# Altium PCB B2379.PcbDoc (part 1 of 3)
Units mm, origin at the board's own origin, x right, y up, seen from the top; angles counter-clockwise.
Board outline 50 x 95 mm, 4 copper layers (Top Layer 1 Signal, Layer 2, Layer 3, Bottom Layer 4 Signal), stack 1.536 mm thick; 177 components, 121 nets, 523 pads, 969 vias.
Unrouted connection lines stored in the file: 25.
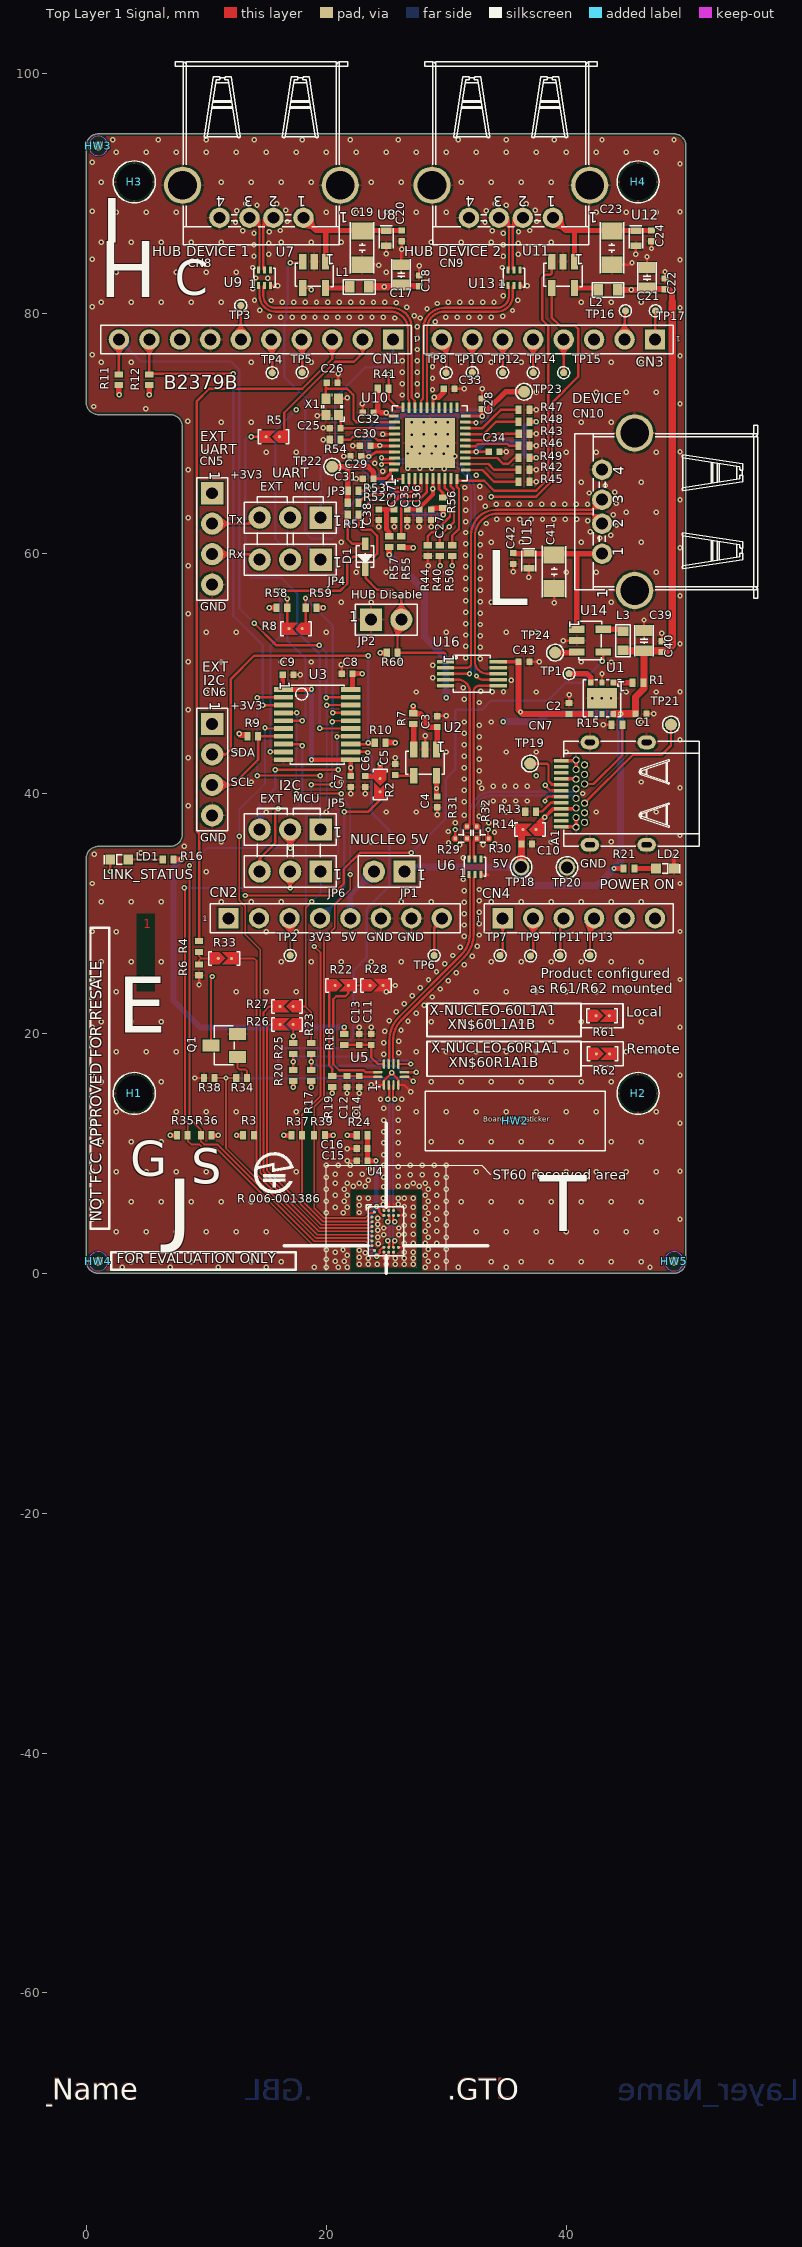
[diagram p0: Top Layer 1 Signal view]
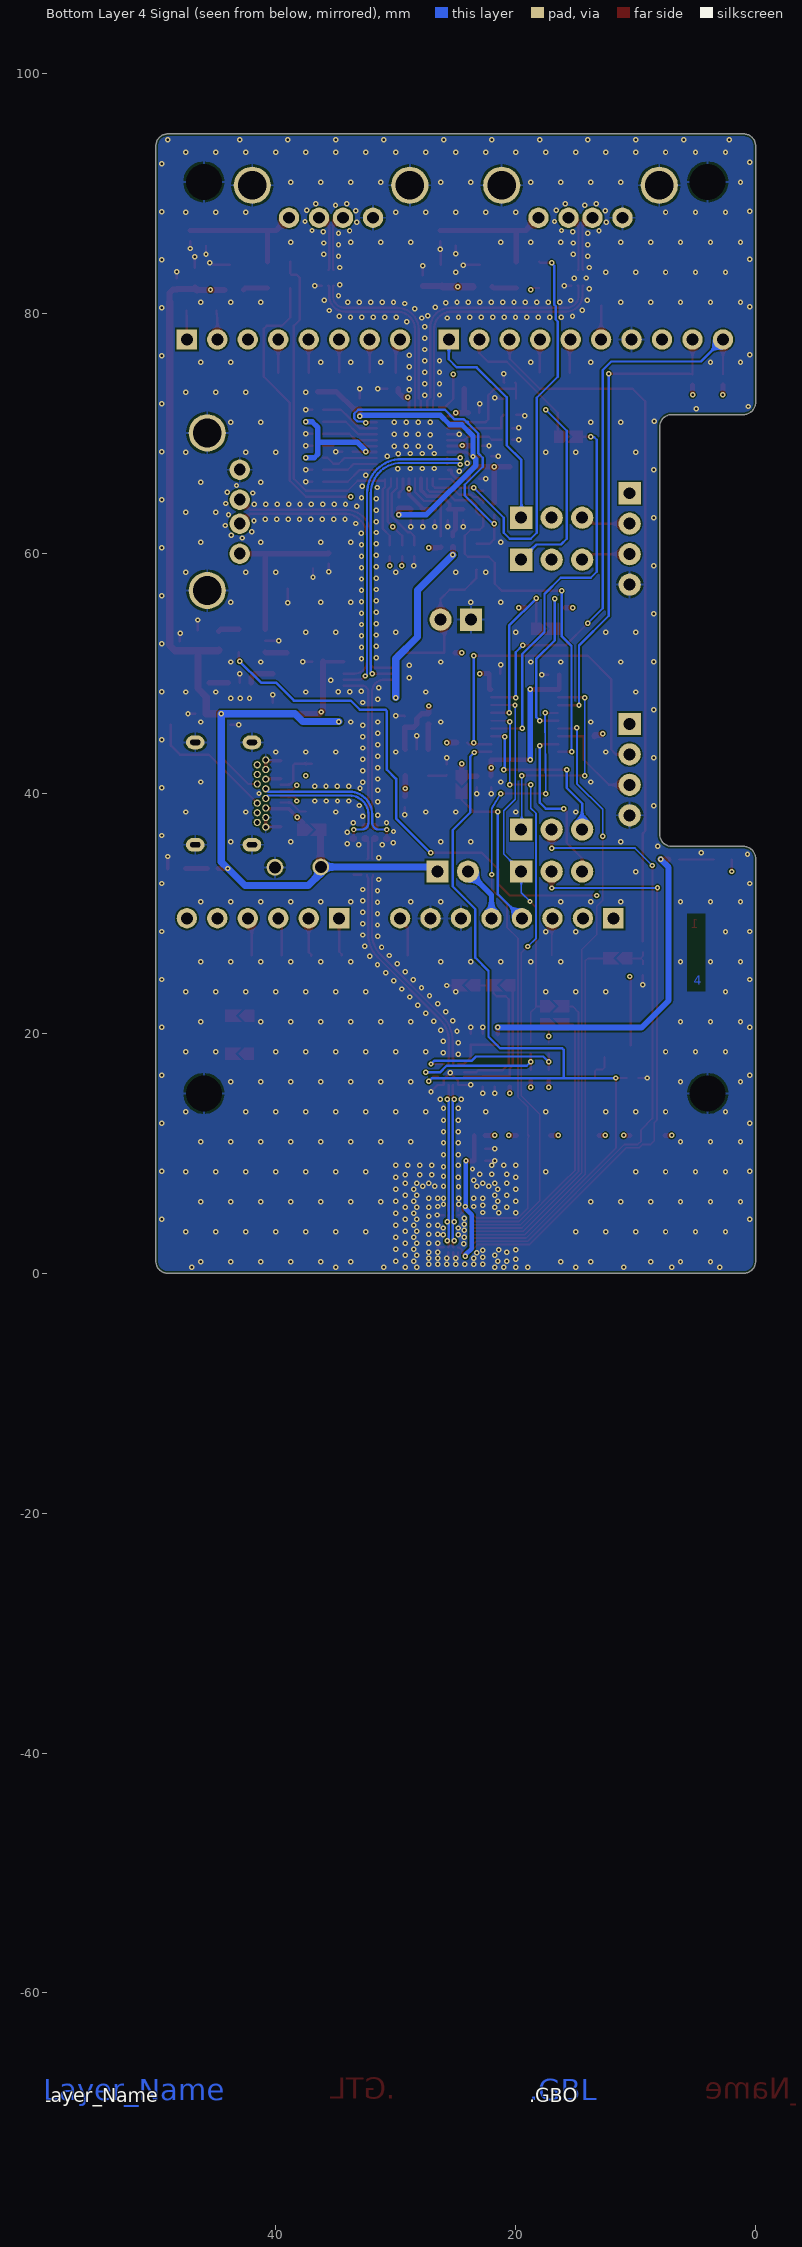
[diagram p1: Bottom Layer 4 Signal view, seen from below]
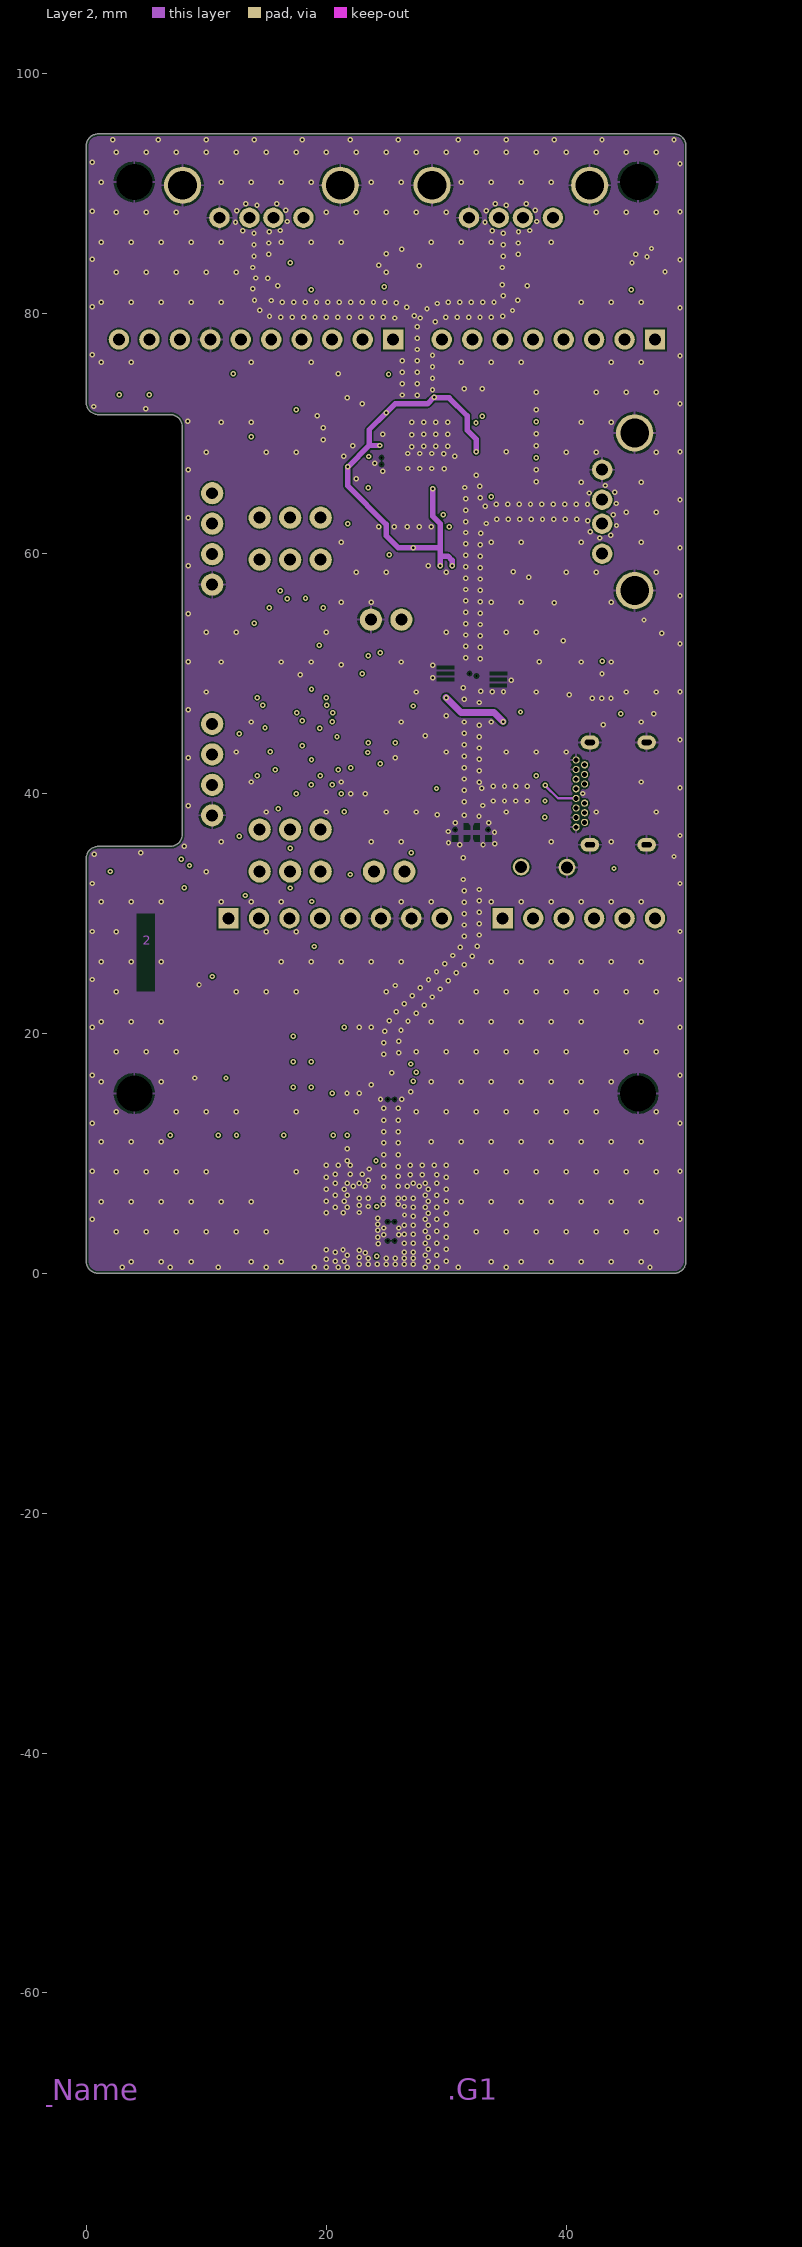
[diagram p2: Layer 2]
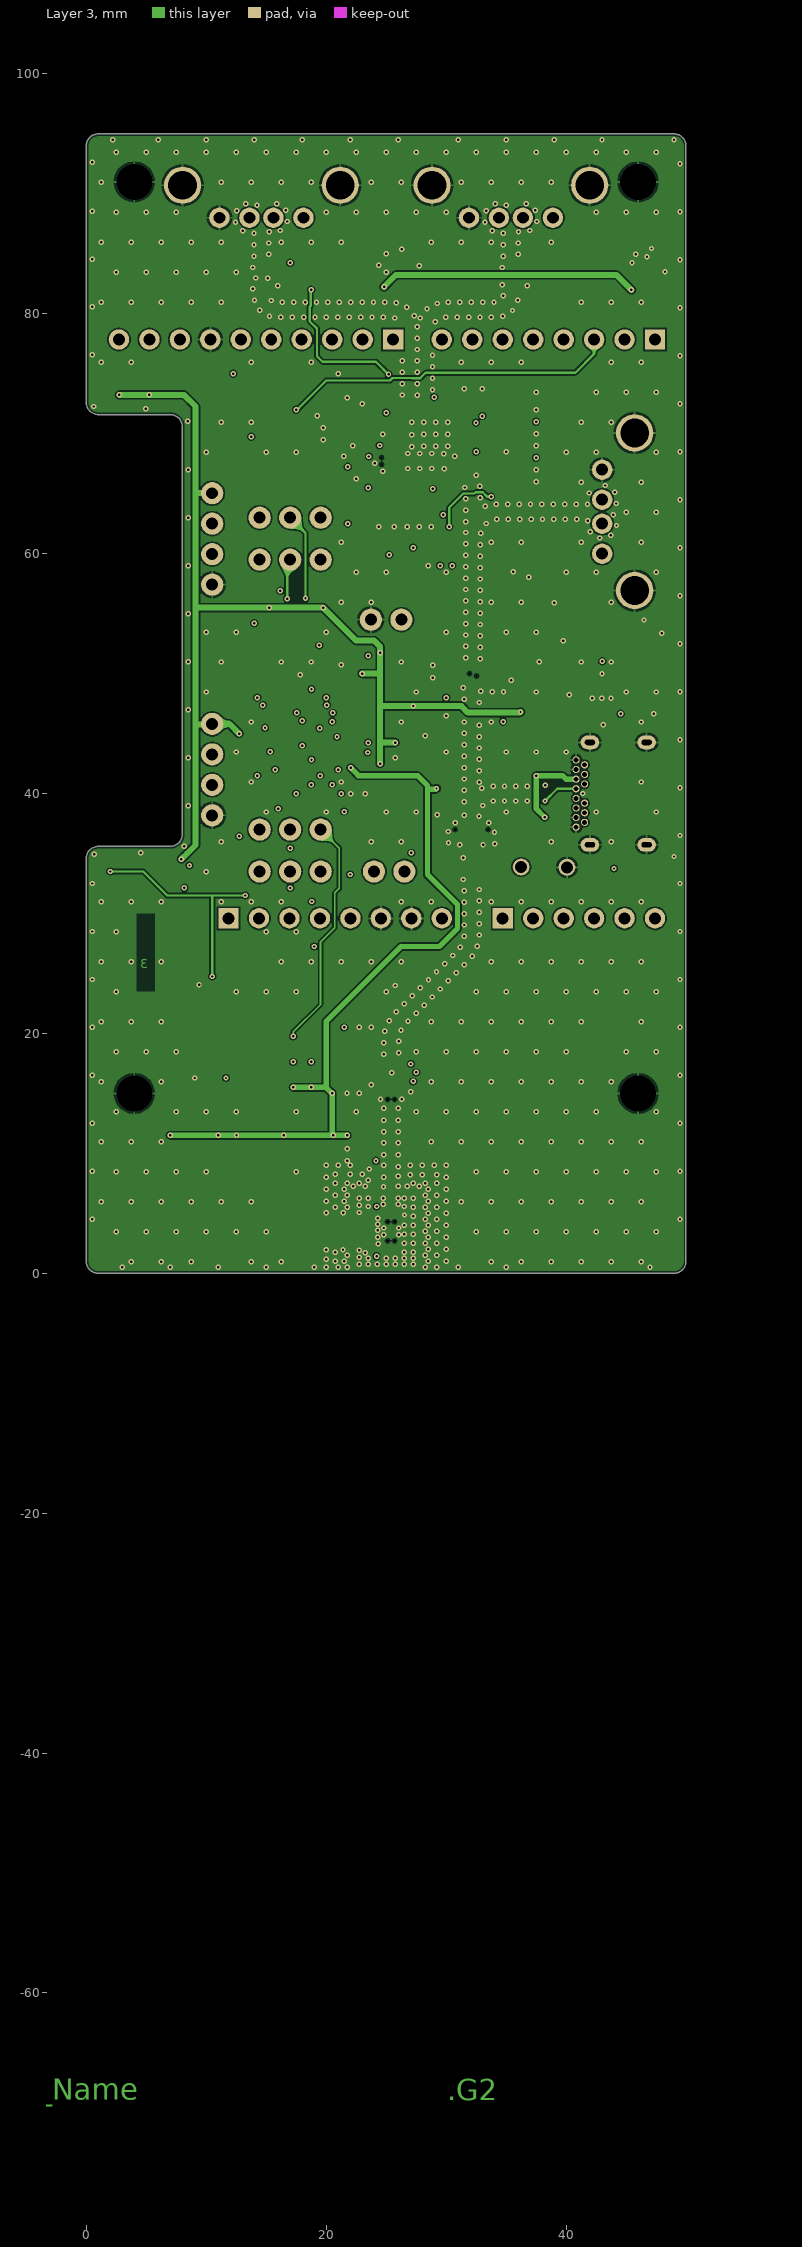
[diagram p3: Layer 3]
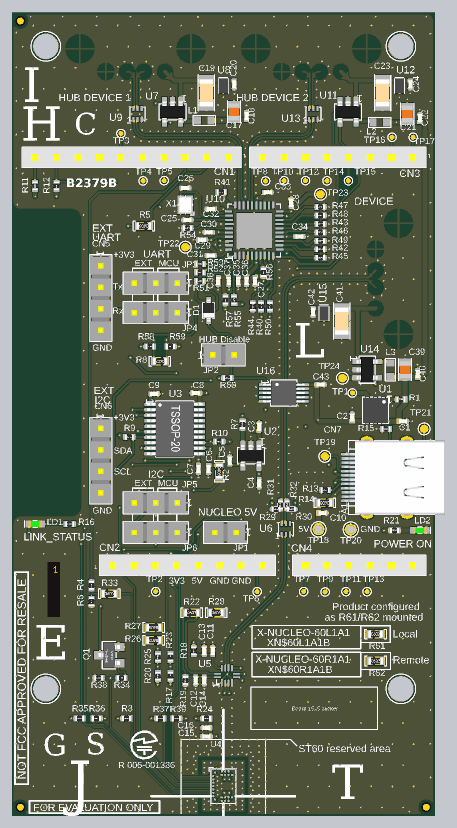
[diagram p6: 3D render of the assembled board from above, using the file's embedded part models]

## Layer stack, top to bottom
Top Solder: solder mask 0.0254, SM-003, Dk 4
Top Layer 1 Signal: signal copper 0.035
Dielectric 1: prepreg 0.36, 2 x 7628, Dk 4.6
Layer 2: signal copper 0.018
Core: core 0.71, CORE- 6 X 7628M, Dk 4.4
Layer 3: signal copper 0.018
Dielectric 2: prepreg 0.36, 2 x 7628, Dk 4.6
Bottom Layer 4 Signal: signal copper 0.035
Bottom Solder: solder mask 0.0254, SM-003, Dk 4

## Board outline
1,0 cw(c1,1) 0,1 0,34.597 cw(c1,34.597) 1,35.597 7,35.597 ccw(c7,36.597) 8,36.597 8,70.597 ccw(c7,70.597) 7,71.597 1,71.597 cw(c1,72.597) 0,72.597 0,94 cw(c1,94) 1,95 49,95 cw(c49,94) 50,94 50,1 cw(c49,1) 49,0

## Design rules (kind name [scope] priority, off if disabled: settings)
BoardOutlineClearance [All] p1: gap=0.2 ignorepadtopadclearanceinfootprint=FALSE
Clearance R29-R_1 [InComponent('R29') vs InComponent('R31')] p1: gap=0 ignorepadtopadclearanceinfootprint=TRUE
Clearance R30-R32 [InComponent('R30') vs InComponent('R32')] p2: gap=0 ignorepadtopadclearanceinfootprint=TRUE
Clearance "Clearance GND" [InNet('GND') vs InNet('GND')] p3: gap=0.1 ignorepadtopadclearanceinfootprint=TRUE except(0: Via-Poly Via-Region)
Clearance Clearance_Default [All] p4: gap=0.127 ignorepadtopadclearanceinfootprint=TRUE except(0: Via-Region; 0.1: Arc-Track Arc-SMDPad SMDPad-Poly THPad-Fill THPad-Region Via-Fill Via-Poly Fill-Fill Fill-Poly Fill-Region Poly-Poly Region-Region)
ComponentClearance [All] p1: gap=0.199 collisioncheckmode=3 verticalgap=2540 showdistances=FALSE donotcheckwithout3dbody=TRUE
DiffPairsRouting "Schematic Differential Pairs Routing" [InDifferentialPairClass('90 Ohms  Zdiff')] p1: maxlimit=0.127 minlimit=0.127 mostfreqgap=0.127 toplayer_minwidth=0.19 toplayer_maxwidth=0.19 toplayer_prefwidth=0.19 midlayer1_minwidth=0.19 midlayer1_maxwidth=0.19 midlayer1_prefwidth=0.19 midlayer2_minwidth=0.19 midlayer2_maxwidth=0.19 midlayer2_prefwidth=0.19 bottomlayer_minwidth=0.19 bottomlayer_maxwidth=0.19 bottomlayer_prefwidth=0.19 impedanceprofiledriven=TRUE impedanceprofileid={3E4A38EC-D2F8-4990-A499-3DF4EA466DCF} impedanceprofilevalue=90.000000 maxuncoupledlength=12.7
FanoutControl Fanout_BGA [IsBGA] p1: bgadir=Out bgaviamode=Closest fanoutstyle=Auto fanoutdirection=Alternating viagrid=0.025 // Fanout_BGA (Default Rule)
FanoutControl Fanout_LCC [IsLCC] p2: bgadir=Out bgaviamode=Closest fanoutstyle=Auto fanoutdirection=Alternating viagrid=0.025 // Fanout_LCC (Default Rule)
FanoutControl Fanout_SOIC [IsSOIC] p3: bgadir=Out bgaviamode=Closest fanoutstyle=Auto fanoutdirection=Alternating viagrid=0.025 // Fanout_SOIC (Default Rule)
FanoutControl Fanout_Small [(CompPinCount < 5)] p4: bgadir=Out bgaviamode=Closest fanoutstyle=Auto fanoutdirection=OutThenIn viagrid=0.025 // Fanout_Small (Default Rule)
FanoutControl Fanout_Default [All] p5: bgadir=Out bgaviamode=Closest fanoutstyle=Auto fanoutdirection=Alternating viagrid=0.025 // Fanout_Default (Default Rule)
Height [All] p1 off: minheight=0 maxheight=2.54 prefheight=0.5
HoleSize [All] p1: absolutevalues=TRUE maxlimit=10 minlimit=0.15 maxpercent=80.000 minpercent=20.000
HoleToHoleClearance [All] p1: gap=0.2 allowstackedmicrovias=TRUE
Length Length_USB [InNetClass('USB')] p1: maxlimit=50 minlimit=1
MatchedLengths [InDifferentialPairClass('DIFF_USB')] p1: tolerance=0.2 checknetsindiffpair=TRUE checkdiffpairvsdiffpair=FALSE checkxsignals=FALSE checkothers=FALSE
MinimumSolderMaskSliver [All] p1: minsoldermaskwidth=0.1
PlaneClearance [All] p1: clearance=0.2
PlaneConnect [All] p1: pad.planeconnectstyle=Relief pad.reliefexpansion=0.45 pad.reliefentries=4 pad.reliefconductorwidth=0.2 pad.reliefairgap=0.2 via.planeconnectstyle=Direct via.reliefexpansion=0.508 via.reliefentries=4 via.reliefconductorwidth=0.254 via.reliefairgap=0.254
PolygonConnect PolygonConnect__DEFAULT [All] p1: thpad.connectstyle=Relief thpad.reliefconductorwidth=0.2 thpad.reliefentries=4 thpad.polygonreliefangle="90 Angle" thpad.airgapwidth=0.2 smdpad.connectstyle=Relief smdpad.reliefconductorwidth=0.2 smdpad.reliefentries=4 smdpad.polygonreliefangle="90 Angle" smdpad.airgapwidth=0.1 via.connectstyle=Direct via.reliefconductorwidth=0.254 via.reliefentries=4 via.polygonreliefangle="45 Angle" via.airgapwidth=0.254
RoutingVias [All] p1: holewidth=0.2 width=0.45 viastyle="Through Hole" minholewidth=0.1 minwidth=0.2 maxholewidth=0.2 maxwidth=0.45
ShortCircuit [All] p1: allowed=TRUE
SilkToSilkClearance [All] p1: silktosilkclearance=0.1
SilkToSolderMaskClearance [IsPad] p1: minsilkscreentomaskgap=0.1 clearancetoexposedcopper=FALSE
SolderMaskExpansion [All] p1: expansion=0 istentingtop=TRUE useseparateexpansions=TRUE expansionbottom=0 istentingbottom=TRUE
UnRoutedNet [All] p1: checkbadconnections=TRUE
Width "Schematic Width Constraint_2" [InNet('+5V')] p1: maxlimit=1 minlimit=0.35 preferedwidth=0.5 midlayer1_maxwidth=0.45 midlayer1_prefwidth=0.4 midlayer2_maxwidth=0.45 midlayer2_prefwidth=0.4 minimp=50.000000 maximp=50.000000 favimp=50.000000
Width "Schematic Width Constraint_1" [InNet('+1V8')] p2: maxlimit=0.45 minlimit=0.25 preferedwidth=0.5
Width "Schematic Width Constraint" [InNet('+3V3')] p3: maxlimit=1 minlimit=0.009 preferedwidth=0.4
Width [All] p4: maxlimit=0.45 minlimit=0.15 preferedwidth=0.2
13 further rules are at their usual default settings.

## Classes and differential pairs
component class USB_Hub: C17 C18 C19 C20 C21 C22 C23 C24 C25 C26 C27 C28 C29 C30 C31 C32 C33 C34 C35 C36 C37 C38 CN8 CN9 D1 JP2 L1 L2 R40 R41 R42 R43 R44 R45 R46 R47 R48 R49 R50 R51 R52 R53 R54 R55 R56 R57 R60 TP22 TP23 U7 U8 U9 U10 U11 U12 U13 X1
component class Switch: C39 C40 C41 C42 C43 CN10 L3 TP24 U14 U15 U16
differential pair class "90 Ohms  Zdiff": D DPU eUSB eUSB_3 eUSB_ST60 eUSB_ST60_3 PTN_RX PTN_USB_HUB PTN_X RX USB1CN USB1CN25 USB2_D2_6 USB2_D3_6 USB2_H1_6 USB2_H2_6 USB2_ST60_3 USB2CN USB2CN25 USB3CN USB5CN USB_1 USB_1_C USB_2 USB_2_C USB_3 USB_D1 USB_D1_5 USB_D2_6 USB_D3_6 USB_D_5 USB_H1_6 USB_H2_6 USB_H_3 USB_HUB USB_HUB1_6 USB_HUB2_6 USB_HUB_B USB_HUB_BYP_5 USB_ST60 USB_ST60_3 USB_ST60_E_3 USBDN1 USBDN2 USBDN3 USBDN4 X
component class ST60A3H1: C10 C11 C12 C13 C14 C15 C16 CN7 LD1 Q1 R13 R14 R15 R16 R17 R18 R19 R20 R22 R23 R24 R25 R26 R27 R28 R29 R30 R31 R32 R34 R35 R36 R37 R38 R39 TP18 TP19 TP20 TP21 U4 U5 U6
component class PIO_POWER: C1 C2 C3 C4 C5 C6 C7 C8 C9 CN1 CN2 CN3 CN4 CN5 CN6 H1 H2 H3 H4 HW2 HW3 HW4 HW5 JP1 JP3 JP4 JP5 JP6 LD2 R1 R2 R3 R4 R5 R6 R7 R8 R9 R10 R11 R12 R21 R33 R58 R59 R61 R62 TP1 TP2 TP3 TP4 TP5 TP6 TP7 TP8 TP9 TP10 TP11 TP12 TP13 TP14 TP15 TP16 TP17 U1 U2 U3
differential pair USB_HUB2_6: +USB_HUB2_6_P -USB_HUB2_6_N
differential pair USB_HUB1_6: +USB_HUB1_6_P -USB_HUB1_6_N
differential pair USB_ST60_E_3: +USB_ST60_E_3_P -USB_ST60_E_3_N
differential pair USB_H2_6: +USB_H2_6_P -USB_H2_6_N
differential pair USB_H1_6: +USB_H1_6_P -USB_H1_6_N
differential pair USB_D_5: +USB_D_5_P -USB_D_5_N
differential pair USB2_ST60_3: +USB2_ST60_3_P -USB2_ST60_3_N
differential pair USB_H_3: +USB_H_3_P -USB_H_3_N
differential pair eUSB_ST60_3: +eUSB_ST60_3_P -eUSB_ST60_3_N
differential pair USB_ST60: +USB_ST60_P -USB_ST60_N
differential pair USB_HUB: +USB_HUB_P -USB_HUB_N

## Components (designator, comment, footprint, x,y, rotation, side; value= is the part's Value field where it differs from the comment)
C1 "Capacitor" C0402 46.25,46.65 r180 top value=1uF
C2 "Capacitor" C0402 40.25,47.1 r270 top value=1uF
C3 "Capacitor" C0402 29.25,46 r270 top value=1uF
C4 "Capacitor" C0402 29.25,39.305 r90 top value=1uF
C5 "Capacitor" C0402 25.75,42 r270 top value=10nF
C6 "Capacitor" C0402 23.25,41 r90 top value=1uF
C7 "Capacitor" C0402 22.05,41 r270 top value=100nF
C8 "Capacitor" C0402 21.75,50 r0 top value=100nF
C9 "Capacitor" C0402 16.825,49.9 r180 top value=100nF
C10 "Capacitor" C0402 36.725,35.8 r180 top value=100nF
C11 "Capacitor" C0402 23.75,19.5 r270 top value=1uF
C12 "Capacitor" C0402 21.735,16 r270 top value=1uF
C13 "Capacitor" C0402 22.75,19.5 r90 top value=100pF
C14 "Capacitor" C0402 22.75,16 r270 top value=100pF
C15 "Capacitor" C0402 23,9.375 r0 top value=100nF
C16 "Capacitor" C0402 23,10.4 r180 top value=100nF
C17 "Capacitor" C0805 26.25,83.25 r270 top value=47uF
C18 "Capacitor" C0402 27.75,82.75 r270 top value=100nF
C19 "Capacitor" C1206_H1P6 23,85.5 r90 top value=220uF
C20 "Capacitor" C0402 26.3,86.5 r90 top value=100nF
C21 "Capacitor" C0805 46.75,83 r270 top value=47uF
C22 "Capacitor" C0402 48.25,82.5 r270 top value=100nF
C23 "Capacitor" C1206_H1P6 43.825,85.5 r90 top value=220uF
C24 "Capacitor" C0402 47.125,86.5 r90 top value=100nF
C25 "Capacitor" C0402 20.75,70.47 r0 top value=6.8pF
C26 "Capacitor" C0402 20.5,74.25 r180 top value=6.8pF
C27 "Capacitor" C0402 28.75,63.25 r90 top value=4.7uF
C28 "Capacitor" C0402 33,72.5 r270 top value=100nF
C29 "Capacitor" C0402 22.475,68.125 r0 top value=100nF
C30 "Capacitor" C0402 23.25,69 r0 top value=100nF
C31 "Capacitor" C0402 23.5,66.25 r0 top value=100nF
C32 "Capacitor" C0402 23.5,71.75 r0 top value=100nF
C33 "Capacitor" C0402 30.25,73.75 r180 top value=100nF
C34 "Capacitor" C0402 34,68.5 r180 top value=100nF
C35 "Capacitor" C0402 26.75,63.25 r90 top value=100nF
C36 "Capacitor" C0402 27.75,63.25 r90 top value=4.7uF
C37 "Capacitor" C0402 25.65,63.25 r90 top value=4.7uF
C38 "Capacitor" C0402 24.39,63.25 r90 top value=100nF
C39 "Capacitor" C0805 46.5,52.75 r270 top value=47uF
C40 "Capacitor" C0402 48,52.25 r270 top value=100nF
C41 "Capacitor" C1206_H1P6 39,58.5 r90 top value=220uF
C42 "Capacitor" C0402 35.6,59.6 r90 top value=100nF
C43 "Capacitor" C0402 36.5,51 r180 top value=100nF
CN1 "Socket 10x1" CON_SAMTEC_SSQ-110-03-F-S 14.15,77.86 r180 top locked
CN2 "Socket 8x1" CON_SAMTEC_SSQ-108-03-F-S 20.75,29.6 r0 top locked
CN3 "Socket 8x1" CON_SAMTEC_SSQ-108-03-F-S 38.53,77.86 r180 top locked
CN4 "Socket 6x1" CON_SAMTEC_SSQ-106-03-F-S 41.07,29.6 r0 top locked
CN5 "Header 4x1" CON_SAMTEC_TSW-104-07-G-S 10.5,61.23 r270 top
CN6 "Header 4x1" CON_SAMTEC_TSW-104-07-G-S 10.5,42 r270 top
CN7 "USB_TYPE_C_Receptacle" CON_USB-TYPEC_WE_632723300011 50.17,40 r90 top value=USB_C_632723300011
CN8 "USB_TypeA_Receptacle_67643-3911" CON_USB-TYPEA_MOLEX_67643-3911_H7P73 14.6,101 r180 top locked value=USB_A_67643-3911
CN9 "USB_TypeA_Receptacle_67643-3911" CON_USB-TYPEA_MOLEX_67643-3911_H7P73 35.4,101 r180 top locked value=USB_A_67643-3911
CN10 "USB_TypeA_Receptacle_67643-3911" CON_USB-TYPEA_MOLEX_67643-3911_H7P73 56,63.5 r90 top locked value=USB_A_67643-3911
D1 "BAT60JFILM" DIO_SOD323 23.25,59.75 r270 top
H1 "POSITION HOLE" NPTH_300 4,15 r0 top locked value=NPTH
H2 "POSITION HOLE" NPTH_300 46,15 r0 top value=NPTH
H3 "POSITION HOLE" NPTH_300 4,91 r0 top value=NPTH
H4 "POSITION HOLE" NPTH_300 46,91 r0 top value=NPTH
HW2 "STICKER_BOARD" STICKER_Board_15X5 35.75,12.7 r0 top value="Sticker board"
HW3 "FiducialPad" MIRE_PLACE_SMD_0P8MM 1,94 r90 top value="Fiducial Pad"
HW4 "FiducialPad" MIRE_PLACE_SMD_0P8MM 1,1 r90 top value="Fiducial Pad"
HW5 "FiducialPad" MIRE_PLACE_SMD_0P8MM 49,1 r90 top value="Fiducial Pad"
JP1 "Jumper_Header 2x1" CON_SAMTEC_TSW-102-07-G-S 25.25,33.5 r180 top value="Header 2x1"
JP2 "Jumper_Header 2x1" CON_SAMTEC_TSW-102-07-G-S 25,54.5 r0 top value="Header 2x1"
JP3 "Jumper_Header 3x1" CON_SAMTEC_TSW-103-07-F-S 17,63 r180 top value="Header 3x1"
JP4 "Jumper_Header 3x1" CON_SAMTEC_TSW-103-07-F-S 17,59.5 r180 top value="Header 3x1"
JP5 "Jumper_Header 3x1" CON_SAMTEC_TSW-103-07-F-S 17,37 r180 top value="Header 3x1"
JP6 "Jumper_Header 3x1" CON_SAMTEC_TSW-103-07-F-S 17,33.5 r180 top value="Header 3x1"
L1 "BEAD" FIL_0603_H0P65 22.75,82.25 r180 top value="26R @ 100Mhz"
L2 "BEAD" FIL_0603_H0P65 43.5,82 r180 top value="26R @ 100Mhz"
L3 "BEAD" FIL_0603_H0P65 44.75,52.75 r90 top value="26R @ 100Mhz"
LD1 "LED_green" LED_0603_GREEN 2.75,34.5 r180 top value=Green
LD2 "LED_green" LED_0603_GREEN 48.25,33.75 r0 top value=Green
Q1 "9013-SOT23" NPN_SOT23 11.5,19 r90 top value="NPN SOT23"
R1 "Resistor" R0402 46,49.25 r180 top value=1K
R2 "Resistor" SOLDER-BRIDGE_R0603-0R 24.5,40.75 r270 top value=0R
R3 "Resistor" R0402 13.53,11.5 r0 top value=10K
R4 "Resistor" R0402 9.4,27.25 r270 top value=1K5
R5 "Resistor" SOLDER-BRIDGE_R0603-0R 15.6,69.75 r180 top value=0R
R6 "Resistor" R0402 9.4,25.302 r90 top value=1K8
R7 "Resistor" R0402 27.25,46.25 r270 top value=1K
R8 "Resistor" SOLDER-BRIDGE_R0603-0R 17.5,53.75 r180 top value=0R
R9 "Resistor" R0402 13.875,44.775 r180 top value=4K7
R10 "Resistor" R0402 24.499,44.25 r0 top value=4K7
R11 "Resistor" R0402 2.72,74.5 r270 top value=4K7
R12 "Resistor" R0402 5.26,74.5 r270 top value=4K7
R13 "Resistor" R0402 37.05,38.5 r0 top value=5K1
R14 "Resistor" SOLDER-BRIDGE_R0603-0R 37,37 r180 top value=0R
R15 "Resistor" R0402 44.25,45.75 r0 top value=5K1
R16 "Resistor" R0402 6.825,34.5 r0 top value=220R
R17 "Resistor" R0402 18.75,16.5 r270 top value=4K7
R18 "Resistor" R0402 21.5,19.5 r90 top value=0R
R19 "Resistor" R0402 20.5,16 r270 top value=0R
R20 "Resistor" R0402 17.25,16.5 r270 top value=4K7
R21 "Resistor" R0402 45.25,33.75 r180 top value=220R
R22 "Resistor" SOLDER-BRIDGE_R0603-0R 21.25,24 r0 top value=0R
R23 "Resistor" R0402 18.75,18.75 r270 top value=0R
R24 "Resistor" R0402 23,11.5 r0 top value=0R
R25 "Resistor" R0402 17.25,18.752 r270 top value=0R
R26 "Resistor" SOLDER-BRIDGE_R0603-0R 16.75,20.75 r180 top value=0R
R27 "Resistor" SOLDER-BRIDGE_R0603-0R 16.75,22.25 r180 top value=0R
R28 "Resistor" SOLDER-BRIDGE_R0603-0R 24.15,24 r0 top value=0R
R29 "Resistor" R0402_BGA 31.247,36.25 r0 top value=0R
R30 "Resistor" R0402_BGA 33.046,36.253 r180 top value=0R
R31 "Resistor" R0402_BGA 31.737,36.752 r270 top value=0R
R32 "Resistor" R0402_BGA 32.545,36.752 r270 top value=0R
R33 "Resistor" SOLDER-BRIDGE_R0603-0R 11.5,26.25 r0 top value=0R
R34 "Resistor" R0402 12.951,16.285 r180 top value=10K
R35 "Resistor" R0402 8,11.5 r180 top value=4K7
R36 "Resistor" R0402 10,11.5 r0 top value=4K7
R37 "Resistor" R0402 17.543,11.5 r180 top value=390R
R38 "Resistor" R0402 10.25,16.285 r0 top value=1K
R39 "Resistor" R0402 19.439,11.5 r0 top value=4K7
R40 "Resistor" R0402 29.475,60.25 r270 top value=10K
R41 "Resistor" R0402 24.75,73.75 r180 top value=10K
R42 "Resistor" R0402 36.5,67 r180 top value=10K
R43 "Resistor" R0402 36.504,70.003 r180 top value=10K
R44 "Resistor" R0402 28.475,60.25 r90 top value=10K
R45 "Resistor" R0402 36.5,66 r180 top value=10K
R46 "Resistor" R0402 36.5,69 r180 top value=10K
R47 "Resistor" R0402 36.5,72 r180 top value=10K
R48 "Resistor" R0402 36.5,71 r0 top value=10K
R49 "Resistor" R0402 36.5,68 r0 top value=10K
R50 "Resistor" R0402 30.5,60.25 r270 top value=10K
R51 "Resistor" R0402 22.25,63.25 r180 top value=10K
R52 "Resistor" R0402 22.25,64.25 r0 top value=0R
R53 "Resistor" R0402 22.25,65.25 r180 top value=10K
R54 "Resistor" R0402 20.75,69.5 r180 top value=1K6
R55 "Resistor" R0402 26.25,61 r270 top value=0R
R56 "Resistor" R0402 29.75,64.25 r90 top value=0R
R57 "Resistor" R0402 25.25,61 r90 top value=0R
R58 "Resistor" R0402 16.3,55.5 r180 top value=4K7
R59 "Resistor" R0402 18.75,55.5 r0 top value=4K7
R60 "Resistor" R0402 25.5,51.75 r180 top value=10K
R61 "Resistor" SOLDER-BRIDGE_R0603-0R 43,21.475 r0 top value=0R
R62 "Resistor" SOLDER-BRIDGE_R0603-0R 43.025,18.3 r0 top value=0R
TP1 "Test Point" TP_SMD_0-6MM 40.25,50 r180 top value=N/A
TP2 "Test Point" TP_SMD_0-6MM 17,26.5 r90 top value=N/A
TP3 "Test Point" TP_SMD_0-6MM 12.88,80.695 r90 top value=N/A
TP4 "Test Point" TP_SMD_0-6MM 15.5,75.088 r90 top value=N/A
TP5 "Test Point" TP_SMD_0-6MM 18,75.119 r90 top value=N/A
TP6 "Test Point" TP_SMD_0-6MM 29,26.5 r90 top value=N/A
TP7 "Test Point" TP_SMD_0-6MM 34.5,26.5 r90 top value=N/A
TP8 "Test Point" TP_SMD_0-6MM 30,75.078 r90 top value=N/A
TP9 "Test Point" TP_SMD_0-6MM 37.038,26.462 r90 top value=N/A
TP10 "Test Point" TP_SMD_0-6MM 32.18,75.105 r90 top value=N/A
TP11 "Test Point" TP_SMD_0-6MM 39.5,26.5 r90 top value=N/A
TP12 "Test Point" TP_SMD_0-6MM 34.72,75.114 r90 top value=N/A
TP13 "Test Point" TP_SMD_0-6MM 42,26.5 r90 top value=N/A
TP14 "Test Point" TP_SMD_0-6MM 37.26,75.096 r90 top value=N/A
TP15 "Test Point" TP_SMD_0-6MM 39.8,75.096 r90 top value=N/A
TP16 "Test Point" TP_SMD_0-6MM 44.95,80.25 r90 top value=N/A
TP17 "Test Point" TP_SMD_0-6MM 47.45,80.25 r90 top value=N/A
TP18 "Test_Point_PTH_1mm_2mm" TP_PTH_1MM_1P4MM 36.25,33.875 r90 top value=TP
TP19 "Test Point" TP_SMD_1MM 37,42.5 r90 top value="Test Point 1mm"
TP20 "Test_Point_PTH_1mm_2mm" TP_PTH_1MM_1P4MM 40.075,33.85 r90 top value=TP
TP21 "Test Point" TP_SMD_1MM 48.75,45.75 r90 top value="Test Point 1mm"
TP22 "Test Point" TP_SMD_1MM 20.5,67.25 r90 top value="Test Point 1mm"
TP23 "Test Point" TP_SMD_1MM 36.5,73.5 r90 top value="Test Point 1mm"
TP24 "Test Point" TP_SMD_1MM 39.088,51.75 r90 top value="Test Point 1mm"
U1 "LD39050PU33R" ICC_DFN6-EPAD_3X3_P095 43,47.95 r180 top
U2 "LD3985M18R" REG_SOT23-5L 28.25,42.575 r180 top
U3 "ST2378ETTR" ICC_TSSOP20_6P50X4P40_P065 19.25,45.75 r270 top locked
U4 "ST60A3G1" ICC_VFBGA23_AiP_2P9X4P1_P040_B2310D 25,3.5 r0 top locked value=ST60A3H1C1CCEPY3
U5 "PTN3222GMJ" ICC_XQFN12_1P75X2P2_P040_SOT2074-1 25.415,16.575 r90 top
U6 "​" ESD_QFN-6L_1P7X1P5_P050 32.396,33.89 r0 top value=ECMF02-2AMX6
U7 "STMPS2161STR" MOS_SOT23-5L 19,83.25 r180 top
U8 "​Footprint needed DFN105P160X60-2N" ESD_QFN1610_2N_1K_2A 25,86.3 r270 top value=ESDA7P120-1U1M
U9 "​" ESD_QFN-6L_1P7X1P5_P050 14.85,83 r0 top value=ECMF02-2AMX6
U10 "UPD720115" ICC_QFN40-EPAD_6X6_P050 28.65,69.225 r90 top locked value=UPD720115K8-711
U11 "STMPS2161STR" MOS_SOT23-5L 39.75,83.25 r180 top
U12 "​Footprint needed DFN105P160X60-2N" ESD_QFN1610_2N_1K_2A 45.825,86.3 r270 top value=ESDA7P120-1U1M
U13 "​" ESD_QFN-6L_1P7X1P5_P050 35.65,83 r0 top value=ECMF02-2AMX6
U14 "STMPS2161STR" MOS_SOT23-5L 42,52.75 r270 top
U15 "​Footprint needed DFN105P160X60-2N" ESD_QFN1610_2N_1K_2A 36.9,59.4 r270 top value=ESDA7P120-1U1M
U16 "TS3USB30E" ICC_VSSOP10_3X3_P050 32.15,50 r270 top value=TS3USB30EDGSR
X1 "XTAL_4_PINS" CRY_NX2016SA_4P 20.5,72.25 r90 top value=24MHz

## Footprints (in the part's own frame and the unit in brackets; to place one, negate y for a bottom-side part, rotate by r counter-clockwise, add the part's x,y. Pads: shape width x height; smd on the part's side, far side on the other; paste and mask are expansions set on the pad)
C0402 [mm]
  rect 0.51x0.56 smd mask+0.05: 1(-0.45,0) 2(0.45,0)
  body extent -0.5,-0.3 0.5,0.3, height 0.4
C0805 [mm]
  rect 0.9x1.4 smd mask+0.05: 1(-0.85,0) 2(0.85,0)
  silkscreen extent -1.3,-0.77 1.3,0.77, body extent -1.1,-0.7 1.1,0.7, height 1.35
C1206_H1P6 [mm]
  rect 1.4x1.78 smd mask+0.05: 1(-1.4,0) 2(1.4,0)
  silkscreen extent -2.12,-0.97 2.15,0.97, body extent -1.7,-0.9 1.7,0.9, height 1.8
CON_SAMTEC_SSQ-106-03-F-S [mm] "MCD-02623"
  rect 1.7x1.7 hole 1 mask+0.05: 1(-6.35,0)
  round 1.7 hole 1 mask+0.05: 2(-3.81,0) 3(-1.27,0) 4(1.27,0) 5(3.81,0) 6(6.35,0)
  silkscreen extent -7.88,-1.21 7.88,1.21, body extent -7.87,-1.21 7.87,1.21, height 8.51
CON_SAMTEC_SSQ-108-03-F-S [mm] "MCD-02624"
  rect 1.7x1.7 hole 1 mask+0.05: 1(-8.89,0)
  round 1.7 hole 1 mask+0.05: 2(-6.35,0) 3(-3.81,0) 4(-1.27,0) 5(1.27,0) 6(3.81,0) 7(6.35,0) 8(8.89,0)
  silkscreen extent -10.41,-1.21 10.41,1.21, body extent -10.41,-1.21 10.41,1.21, height 8.51
CON_SAMTEC_SSQ-110-03-F-S [mm] "MCD-02625"
  rect 1.7x1.7 hole 1 mask+0.05: 1(-11.43,0)
  round 1.7 hole 1 mask+0.05: 2(-8.89,0) 3(-6.35,0) 4(-3.81,0) 5(-1.27,0) 6(1.27,0) 7(3.81,0) 8(6.35,0) 9(8.89,0) 10(11.43,0)
  silkscreen extent -12.95,-1.21 12.95,1.21, body extent -12.95,-1.21 12.95,1.21, height 8.51
CON_SAMTEC_TSW-102-07-G-S [mm]
  rect 1.85x1.85 / inner round 1.85 / far side rect 1.85x1.85 hole 1 mask+0.05: 1(-1.27,0)
  round 1.85 hole 1 mask+0.05: 2(1.27,0)
  silkscreen extent -2.58,-1.3 2.58,1.3, body extent -2.67,-1.3 2.58,1.3, height 8.38
CON_SAMTEC_TSW-103-07-F-S [mm]
  rect 1.85x1.85 / inner round 1.85 / far side rect 1.85x1.85 hole 1 mask+0.05: 1(-2.54,0)
  round 1.85 hole 1 mask+0.05: 2(0,0) 3(2.54,0)
  silkscreen extent -3.85,-1.3 3.85,1.3, body extent -3.94,-1.37 3.91,1.37, height 8.38
CON_SAMTEC_TSW-104-07-G-S [mm]
  rect 1.85x1.85 / inner round 1.85 / far side rect 1.85x1.85 hole 1 mask+0.05: 1(-3.81,0)
  round 1.85 hole 1 mask+0.05: 2(-1.27,0) 3(1.27,0) 4(3.81,0)
  silkscreen extent -5.12,-1.3 5.12,1.3, body extent -5.21,-1.37 5.18,1.37, height 8.38
CON_USB-TYPEA_MOLEX_67643-3911_H7P73 [mm] "MCD-01475"
  round 1.7 hole 1 mask+0.1: 1(-3.5,12.99) 2(-1,12.99) 3(1,12.99) 4(3.5,12.99)
  round 3.1 hole 2.4 mask+0.1: 5(-6.57,10.28) 6(6.57,10.28)
  silkscreen extent -7.2,0 7.2,15.26, body extent -8,-0.01 8,15.26, height 8.03
CON_USB-TYPEC_WE_632723300011 [mm]
  rect 0.3x1.2 smd mask+0.05: A1(-2.75,10.58) A2(-2.25,10.58) A3(-1.75,10.58) A4(-1.25,10.58) A5(-0.75,10.58) A6(-0.25,10.58) A7(0.25,10.58) A8(0.75,10.58) A9(1.25,10.58) A10(1.75,10.58) A11(2.25,10.58) A12(2.75,10.58)
  round 0.6 hole 0.4 mask+0.05: B1(2,9.33) B1(2.8,9.33) B2(2.4,8.62) B3(1.6,8.62) B4(1.2,9.33) B5(0.8,8.62) B6(0.4,9.33) B7(-0.4,9.33) B8(-0.8,8.62) B9(-1.2,9.33) B10(-1.6,8.62) B11(-2.4,8.62) B12(-2.8,9.33) B12(-2,9.33)
  oval 1.15x1.55 hole 0.45 slot 0.85 at 90 deg mask+0.05: SH1(-4.27,8.18) SH2(-4.27,3.45) SH3(4.27,8.18) SH4(4.27,3.45)
  silkscreen extent -4.38,-0.95 4.38,10.38, body extent -4.38,-0.98 4.38,10.82, height 3.03
CRY_NX2016SA_4P [mm]
  rect 0.85x0.75 smd mask+0.05: 1(-0.675,-0.525) 2(0.675,-0.525) 3(0.675,0.525) 4(-0.675,0.525)
  silkscreen extent -1.22,-1.02 1.05,0.85, body extent -1.05,-0.85 1.05,0.85, height 0.7
DIO_SOD323 [mm]
  rect 1.06x0.54 smd mask+0.05: 1(-1.07,0) 2(1.07,0)
  silkscreen extent -0.9,-0.72 0.9,0.72, body extent -1.3,-0.78 1.3,0.78, height 1.17
ESD_QFN1610_2N_1K_2A [mm] "DFN, 2-Leads, Body 1.60x1.00mm"
  rect 0.55x0.9 smd mask+0.05: 1(-0.625,0) 2(0.625,0)
  silkscreen extent -1.02,-0.58 0.85,0.58, body extent -0.85,-0.55 0.85,0.55, height 0.6
ESD_QFN-6L_1P7X1P5_P050 [mm]
  rect 0.25x0.6 smd mask+0.05: 1(-0.5,-0.65) 2(0,-0.65) 3(0.5,-0.65) 4(0.5,0.65) 5(0,0.65) 6(-0.5,0.65)
  silkscreen extent -0.9,-0.8 0.9,0.8, body extent -0.9,-0.8 0.9,0.8, height 0.56
FIL_0603_H0P65 [mm]
  rect 0.8x0.95 smd mask+0.05: 1(-0.8,0) 2(0.8,0)
  silkscreen extent -1.33,-0.6 1.33,0.6, body extent -0.87,-0.47 0.87,0.47, height 0.65
ICC_DFN6-EPAD_3X3_P095 [mm]
  rect 0.45x0.5 smd mask+0.05: 1(-0.95,-1.3) 2(0,-1.3) 3(0.95,-1.3) 4(0.95,1.3) 5(0,1.3) 6(-0.95,1.3)
  rect 2.5x1.7 smd mask+0.05: EP(0,0)
  silkscreen extent -1.55,-1.55 1.55,1.55, body extent -1.55,-1.55 1.55,1.55, height 1
ICC_QFN40-EPAD_6X6_P050 [mm]
  rect 0.8x0.25 smd mask+0.05: 1(-3,2.25) 10(-3,-2.25) 21(3,-2.25) 30(3,2.25)
  rect 0.9x0.25 smd mask+0.05: 2(-2.95,1.75) 3(-2.95,1.25) 4(-2.95,0.75) 5(-2.95,0.25) 6(-2.95,-0.25) 7(-2.95,-0.75) 8(-2.95,-1.25) 9(-2.95,-1.75) 22(2.95,-1.75) 23(2.95,-1.25) 24(2.95,-0.75) 25(2.95,-0.25) 26(2.95,0.25) 27(2.95,0.75) 28(2.95,1.25) 29(2.95,1.75)
  rect 0.25x0.8 smd mask+0.05: 11(-2.25,-3) 20(2.25,-3) 31(2.25,3) 40(-2.25,3)
  rect 0.25x0.9 smd mask+0.05: 12(-1.75,-2.95) 13(-1.25,-2.95) 14(-0.75,-2.95) 15(-0.25,-2.95) 16(0.25,-2.95) 17(0.75,-2.95) 18(1.25,-2.95) 19(1.75,-2.95) 32(1.75,2.95) 33(1.25,2.95) 34(0.75,2.95) 35(0.25,2.95) 36(-0.25,2.95) 37(-0.75,2.95) 38(-1.25,2.95) 39(-1.75,2.95)
  rect 4.15x4.15 smd mask+0.05: 41(0,0)
  silkscreen extent -3.15,-3.13 3.13,3.13, body extent -3,-3 3,3, height 0.91
ICC_TSSOP20_6P50X4P40_P065 [mm]
  rect 0.4x1.6 smd mask+0.05: 1(-2.925,-2.8) 2(-2.275,-2.8) 3(-1.625,-2.8) 4(-0.975,-2.8) 5(-0.325,-2.8) 6(0.325,-2.8) 7(0.975,-2.8) 8(1.625,-2.8) 9(2.275,-2.8) 10(2.925,-2.8) 11(2.925,2.8) 12(2.275,2.8) 13(1.625,2.8) 14(0.975,2.8) 15(0.325,2.8) 16(-0.325,2.8) 17(-0.975,2.8) 18(-1.625,2.8) 19(-2.275,2.8) 20(-2.925,2.8)
  silkscreen extent -3.3,-2.25 3.3,2.25, body extent -3.3,-3.3 3.3,3.3, height 1.21
ICC_VFBGA23_AiP_2P9X4P1_P040_B2310D [mm] "MCD-03321"
  round 0.25 smd mask+0.038: A3(-0.185,1.73) A4(0.215,1.73) A5(0.615,1.73) B2(-0.975,1.6) C3(-0.185,1.33) C4(0.215,1.33) C5(0.615,1.33) C6(1.015,1.33) D1(-1.175,1.2) E1(-1.175,0.8) F1(-1.175,0.4) G1(-1.175,0) H1(-1.175,-0.4) J1(-1.175,-0.8) K1(-1.175,-1.2) L3(-0.185,-1.33) L4(0.215,-1.33) L5(0.615,-1.33) L6(1.015,-1.33) M2(-0.975,-1.6) N3(-0.185,-1.73) N4(0.215,-1.73) N5(0.615,-1.73)
  Top Layer 1 Signal pour cut-out: -0.185,1.09 1.032,1.09 1.136,1.113 1.224,1.175 1.224,1.174 1.273,1.249 1.291,1.336 1.291,1.336 1.291,1.345 1.271,1.445 1.214,1.53 1.214,1.53 1.195,1.549 1.004,1.736 0.813,1.922 0.805,1.93 0.728,1.982 0.637,2 0.637,2 -0.135,2 -0.195,1.994 -0.253,1.981 -0.253,1.981 -0.296,1.952 -0.338,1.924 -0.395,1.838 -0.405,1.788 -0.41,1.72 -0.41,1.32 -0.406,1.266 -0.398,1.224 -0.351,1.154 -0.28,1.107
  Top Layer 1 Signal pour cut-out: -0.185,-1.09 1.032,-1.09 1.136,-1.113 1.223,-1.175 1.223,-1.174 1.273,-1.249 1.29,-1.336 1.29,-1.336 1.29,-1.345 1.27,-1.445 1.213,-1.53 1.214,-1.53 1.195,-1.549 1.004,-1.736 0.813,-1.922 0.805,-1.93 0.728,-1.982 0.636,-2 0.636,-2 -0.135,-2 -0.195,-1.994 -0.253,-1.981 -0.253,-1.981 -0.296,-1.952 -0.339,-1.924 -0.396,-1.838 -0.406,-1.788 -0.41,-1.72 -0.41,-1.32 -0.406,-1.266 -0.398,-1.224 -0.351,-1.154 -0.281,-1.107
  Top Layer 1 Signal pour cut-out: -1.406,-1.212 -1.4,1.232 -1.4,1.247 -1.349,1.505 -1.202,1.724 -1.202,1.724 -1.163,1.764 -1.078,1.82 -0.979,1.839 -0.979,1.839 -0.89,1.822 -0.814,1.771 -0.814,1.771 -0.762,1.693 -0.744,1.601 -0.744,1.601 -0.744,1.596 -0.764,1.493 -0.822,1.406 -0.822,1.406 -0.904,1.352 -0.918,1.338 -0.942,1.302 -0.95,1.26 -0.95,1.26 -0.95,-1.19 -0.95,-1.222 -0.938,-1.281 -0.904,-1.332 -0.904,-1.332 -0.825,-1.385 -0.768,-1.47 -0.748,-1.57 -0.748,-1.57 -0.748,-1.601 -0.762,-1.668 -0.799,-1.724 -0.799,-1.724 -0.852,-1.776 -0.89,-1.802 -0.934,-1.811 -0.934,-1.811 -0.982,-1.811 -1.077,-1.792 -1.158,-1.738 -1.158,-1.738 -1.21,-1.685 -1.355,-1.468 -1.406,-1.212
  silkscreen extent -1.68,-2.03 1.48,2.23, body extent -1.5,-2.06 1.5,2.06, height 0.81
ICC_VSSOP10_3X3_P050 [mm] "MCD-02208"
  rect 0.3x1.45 smd paste+0 mask+0.05: 1(-1,-2.2) 2(-0.5,-2.2) 3(0,-2.2) 4(0.5,-2.2) 5(1,-2.2) 6(1,2.2) 7(0.5,2.2) 8(0,2.2) 9(-0.5,2.2) 10(-1,2.2)
  silkscreen extent -1.55,-1.55 1.55,1.55, body extent -1.55,-2.46 1.55,2.46, height 1.1
ICC_XQFN12_1P75X2P2_P040_SOT2074-1 [mm] "MCD-03404"
  rrect100% 0.8x0.2 smd mask+0.05: 1(-0.875,0.6) 2(-0.875,0.2) 3(-0.875,-0.2) 4(-0.875,-0.6) 7(0.875,-0.6) 8(0.875,-0.2) 9(0.875,0.2) 10(0.875,0.6)
  rrect100% 0.2x0.8 smd mask+0.05: 5(-0.2,-1.1) 6(0.2,-1.1) 11(0.2,1.1) 12(-0.2,1.1)
  silkscreen extent -1,0.9 -0.5,1.22, body extent -0.87,-1.1 0.87,1.1, height 0.51
LED_0603_GREEN [mm]
  rect 0.8x0.8 smd mask+0.05: 1(-0.75,0) 2(0.75,0)
  silkscreen extent -0.25,-0.4 1.25,0.4, body extent -0.8,-0.4 0.8,0.4, height 0.6
MIRE_PLACE_SMD_0P8MM [mm]
  round 0.8 smd paste-10 mask+0.2: 1(0,0)
  Top Layer 1 Signal keep-out circle w0.01: c0,0 r0.804
MOS_SOT23-5L [mm]
  rect 0.6x1.3 smd mask+0.05: 1(-0.95,-1.1) 2(0,-1.1) 3(0.95,-1.1) 4(0.95,1.1) 5(-0.95,1.1)
  silkscreen extent -1.6,-0.95 1.6,0.97, body extent -1.52,-1.25 1.52,1.25, height 1.45
NPN_SOT23 [mm]
  rect 1x1.4 smd mask+0.05: 1(-0.95,-1.1) 2(0.95,-1.1) 3(0,1.1)
  silkscreen extent -1.63,-0.82 1.63,0.82, body extent -1.56,-1.25 1.56,1.25, height 1.1
NPTH_300 [mm]
  round 0 hole 3 mask+0.05: 1(0,0)
  silkscreen extent -1.75,-1.75 1.75,1.75
R0402 [mm]
  rect 0.51x0.7 smd mask+0.05: 1(-0.45,0) 2(0.45,0)
  body extent -0.52,-0.3 0.52,0.3, height 0.4
R0402_BGA [mil]
  rrect0% 12x12 smd mask+4: 1(-19.69,0) 2(19.68,0)
  Top Layer 1 Signal region: -30.69,5 -24.69,11 -14.69,11 -8.69,5 -8.69,-5 -14.69,-11 -24.69,-11 -30.69,-5
  Top Layer 1 Signal region: 8.68,5 14.68,11 24.68,11 30.68,5 30.68,-5 24.68,-11 14.68,-11 8.68,-5
  silkscreen extent -10,-12 10,12, body extent -20,-12 20,12, height 13
REG_SOT23-5L [mm]
  rect 0.6x1.3 smd mask+0.05: 1(-0.95,-1.1) 2(0,-1.1) 3(0.95,-1.1) 4(0.95,1.1) 5(-0.95,1.1)
  silkscreen extent -1.6,-0.95 1.6,0.97, body extent -1.52,-1.25 1.52,1.25, height 1.1
SOLDER-BRIDGE_R0603-0R [mil]
  round 10 smd paste-393.7: 1(-19.68,0) 2(23.62,0)
  Top Layer 1 Signal region: -5.91,19.68 13.78,0 -5.91,-19.68 47.24,-19.68 47.24,19.68
  Top Layer 1 Signal region: -47.24,-19.68 -47.24,19.68 -15.75,19.68 3.94,0 -15.75,-19.68
  silkscreen extent -50,-23 50,23, body extent -36,-20 36,20, height 22
STICKER_Board_15X5 [mm] "Sticker to mention board CPN code"
  silkscreen extent -7.5,-2.5 7.5,2.5, body extent -7.5,-2.5 7.5,2.5, height 0.01
TP_PTH_1MM_1P4MM [mm] "MCD-03401"
  round 1.4 hole 1 mask+0.05: 1(0,0)
  silkscreen extent -0.9,-0.9 0.9,0.9
TP_SMD_0-6MM [mm]
  round 0.6 smd paste-10 mask+0.05: 1(0,0)
  silkscreen extent -0.5,-0.5 0.5,0.5
TP_SMD_1MM [mm]
  round 1 smd paste-10 mask+0.05: 1(0,0)
  silkscreen extent -0.7,-0.7 0.7,0.7

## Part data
C1 C2 C3 C4 C6 C11 C12: library part MCD-03432, "Capacitor, MLCC, 1uF, 6.3V, X5R, +/- 10%, 0402, T=0.5mm", Manufacturer=MURATA, Manufacturer_Part_Number=GRM155R70J105KA12, Package=0402
C5: library part MCD-02198, "Capacitor, MLCC, 10nF, 50V, X7R, +/-10%, 0402, T=0.5mm", Manufacturer=YAGEO, Manufacturer_Part_Number=CC0402KRX7R9BB103, Package=0402
C7 C8 C9 C10 C15 C16 C18 C20 C22 C24 C28 C29 C30 C31 C32 C33 C34 C35 C38 C40 C42 C43: library part MCD-00006, "Capacitor, MLCC, 100nF, 16V, X7R, +/-10%, 0402, T=0.5mm", Manufacturer=YAGEO, Manufacturer_Part_Number=CC0402KRX7R7BB104, Package=0402
C13 C14: library part MCD-00205, "Capacitor, MLCC, 100pF, 50V, NPO, +/-5%, 0402, T=0.5mm", Manufacturer=YAGEO, Manufacturer_Part_Number=CC0402JRNPO9BN101, Package=0402
C17 C21 C39: library part MCD-00204, "Capacitor, MLCC, 47uF, 10V, X5R, +/-20%, 0805, T=1.25mm", Manufacturer=MURATA, Manufacturer_Part_Number=GRM21BR61A476ME15K, Package=0805
C19 C23 C41: library part MCD-00104, "Capacitor, MLCC, 220uF, 6V3, X5R, +/-20%, 1206, T=1.6mm", Manufacturer=MURATA, Manufacturer_Part_Number=GRM31CR60J227ME11, Package=1206
C25 C26: library part MCD-00674, "Capacitor, MLCC, 6.8pF, 50V, NPO, +/-0.25pF, 0402, T=0.5mm", Manufacturer=YAGEO, Manufacturer_Part_Number=CC0402CRNPO9BN6R8, Package=0402
C27 C36 C37: library part MCD-01356, "Capacitor, MLCC, 4.7uF, 6V3, X5R, +/-20%, 0402, T=0.5mm", Manufacturer=MURATA, Manufacturer_Part_Number=GRM155R60J475ME47, Package=0402
CN1: library part MCD-02625, "Socket, 10x1, 2.54mm, VR, TH, T=8.51mm/10mm", Manufacturer=SAMTEC, Manufacturer_Part_Number=SSQ-110-03-F-S
CN2 CN3: library part MCD-02624, "Socket, 8x1, 2.54mm, VR, TH, T=8.51mm/10mm", Manufacturer=SAMTEC, Manufacturer_Part_Number=SSQ-108-03-F-S
CN4: library part MCD-02623, "Socket, 6x1, 2.54mm, VR, TH, T=8.51mm/10mm", Manufacturer=SAMTEC, Manufacturer_Part_Number=SSQ-106-03-F-S
CN5 CN6: library part MCD-00029, "Header, 4x1, 2.54mm, VR, TH, T=5.84mm/2.54mm", Manufacturer=SAMTEC, Manufacturer_Part_Number=TSW-104-07-G-S
CN7: library part MCD-02273, "Connector_USB_TypeC, 24pins, RA, TH, T=1.9mm (USB certified)", Manufacturer="WURTH ELEKTRONIK", Manufacturer_Part_Number=632723300011
CN8 CN9 CN10: library part MCD-01475, "USB_TypeA, RA, TH, T= 7.73mm (USB certified)", Manufacturer=MOLEX, Manufacturer_Part_Number=67643-3911
D1: library part MCD-00034, "Diode, Schottky, 0V53, 1A, 10V, SOD323", Manufacturer=STMICROELECTRONICS, Manufacturer_HQ_COO=EU, Package=SOD323
H1 H2 H3 H4: library part RFC-00044, "POSITION HOLE C3R0D3R0", Manufacturer=N/A
HW2: library part MCD-02192, "Sticker board 15x5 mm", Manufacturer=N/A
HW3 HW4 HW5: library part MCD-03135, "Fiducial Pad, 0.8mm", Manufacturer=N/A
JP1 JP2: library part MCD-00045, "Header, 2x1, 2.54mm, VR, TH, T=5.84mm/2.54mm", Manufacturer=SAMTEC, Manufacturer_Part_Number=TSW-102-07-G-S
JP3 JP4 JP5 JP6: library part MCD-00111, "Header, 3x1, 2.54mm, VR, TH, T=5.84mm/2.54mm", Manufacturer=SAMTEC, Manufacturer_Part_Number=TSW-103-07-F-S
L1 L2 L3: library part MCD-00305, "Ferrite bead, 26R @ 100Mhz, +/-25%, 6000mA, 0R007, 0603, T=0.75mm", Manufacturer=MURATA, Manufacturer_Part_Number=BLM18KG260TN1, Package=0603
LD1 LD2: library part MCD-02900, "LED, Green, 2V, 20mA, 0603", Manufacturer=EVERLIGHT, Manufacturer_Part_Number=19-213SYGC/S530-E2/5T, Package=0603
Q1: library part MCD-00073, "NPN Bipolar Transistor", Manufacturer="ON SEMICONDUCTOR", Manufacturer_Part_Number=BSR14, Package=SOT23
R1 R7 R38: library part MCD-00061, "Resistor, 1K, 0402, +/-1%,1/16W", Manufacturer=YAGEO, Manufacturer_Part_Number=RC0402FR-071KL, Package=0402
R2 R5 R8 R14 R22 R26 R27 R28 R33 R61 R62: library part MCD-00056, "Resistor, 0R, 0603, +/-5%, 1/10W", Manufacturer=YAGEO, Manufacturer_Part_Number=RC0603JR-070RL, Package=0603
R3 R34 R40 R41 R42 R43 R44 R45 R46 R47 R48 R49 R50 R51 R53 R60: library part MCD-00053, "Resistor, 10K, 0402, +/-1%, 1/16W", Manufacturer=YAGEO, Manufacturer_Part_Number=RC0402FR-0710KL, Package=0402
R4: library part MCD-00068, "Resistor, 1K5, 0402, +/-1%, 1/16W", Manufacturer=YAGEO, Manufacturer_Part_Number=RC0402FR-071K5L, Package=0402
R6: library part MCD-00409, "Resistor, 1K8, 0402, +/-1%, 1/16W", Manufacturer=YAGEO, Manufacturer_Part_Number=RC0402FR-071K8L, Package=0402
R9 R10 R11 R12 R17 R20 R35 R36 R39 R58 R59: library part MCD-00065, "Resistor, 4K7, 0402, +/-1%, 1/16W", Manufacturer=YAGEO, Manufacturer_Part_Number=RC0402FR-074K7L, Package=0402
R13 R15: library part MCD-00333, "Resistor, 5K1, 0402, +/-1%, 1/16W", Manufacturer=YAGEO, Manufacturer_Part_Number=RC0402FR-075K1L, Package=0402
R16 R21: library part MCD-00427, "Resistor, 220R, 0402, +/-1%, 1/16W", Manufacturer=YAGEO, Manufacturer_Part_Number=RC0402FR-07220RL, Package=0402
R18 R19 R23 R24 R25 R29 R30 R31 R32 R52 R55 R56 R57: library part MCD-00052, "Resistor, 0R, 0402, +/-5%, 1/16W", Manufacturer=YAGEO, Manufacturer_Part_Number=RC0402JR-070RL, Package=0402
R37: library part MCD-00467, "Resistor, 390R, 0402, +/-1%, 1/16W", Manufacturer=YAGEO, Manufacturer_Part_Number=RC0402FR-07390RL, Package=0402
R54: library part MCD-00401, "Resistor, 1K6, 0402, +/-1%, 1/16W", Manufacturer=YAGEO, Manufacturer_Part_Number=RC0402FR-071K6L, Package=0402
TP1 TP2 TP3 TP4 TP5 TP6 TP7 TP8 TP9 TP10 TP11 TP12 TP13 TP14 TP15 TP16 TP17: library part MCD-00631, "Test Point 0.6mm", Manufacturer=N/A
TP18 TP20: library part MCD-03401, "Test Point trought hole 1mm/1.4mm", Manufacturer=N/A
TP19 TP21 TP22 TP23 TP24: library part MCD-00074, "Test Point 1mm", Manufacturer=N/A, Manufacturer_HQ_COO=Unknown
U1: library part MCD-00215, "LDO, 500mA, Low quiescent current and low noise voltage regulator", Manufacturer=STMICROELECTRONICS, Package=DFN-6
U2: library part MCD-00078, "LDO, Ultra low drop and low noise BiCMOS voltage regulators", Manufacturer=STMICROELECTRONICS, Manufacturer_HQ_COO=EU, Package=SOT23-5
U3: library part MCD-03858, "Translator, 8-bit, dual supply 1.71 V to 5.5 V, I/O VCC +/-15 kV ESD protection", Manufacturer=STMICROELECTRONICS, Package=TSSOP-20
U4: library part MCD-03857, "Transceiver, 60GHz, V-band contactless connectivity, with eUSB2, UART, GPIO, or I2C tunneling, VDDIO 1V8", Manufacturer=STMICROELECTRONICS, Manufacturer_Part_Number=ST60A3H1C1CCEPY3, Package=VFBGA-23
U5: library part MCD-03404, "1-port PTN3222 implements Repeater mode (eUSB2 to USB2 redriver)", Manufacturer=NXP, Package=XQFN12_1.75x2.2
U6 U9 U13: library part MCD-00649, "Diode, ESD protection, 1V5, 100nA, 6V, QFN-6", Manufacturer=STMICROELECTRONICS, Manufacturer_HQ_COO=EU, Manufacturer_Part_Number=ECMF02-2AMX6, Package=QFN-6
U7 U11 U14: library part MCD-01167, "Switch, Enhanced single channel power switches", Manufacturer=STMICROELECTRONICS, Manufacturer_HQ_COO=EU, Package=SOT23-5
U8 U12 U15: library part MCD-01026, "Diode, ESD TVS, 5V5, 1.5uA, 6V8, QFN1610", Manufacturer=STMICROELECTRONICS, Manufacturer_HQ_COO=EU, Manufacturer_Part_Number=ESDA7P120-1U1M, Package=QFN1610
U10: library part MCD-03908, "IC, USB 2.0, 4 ports, Hi-Speed hub controller, -40° To +85°", Manufacturer="RENESAS ELECTRONICS", Manufacturer_Part_Number=UPD720115K8-711, Package=QFN-40
U16: library part MCD-02208, "USB Switch, ESD-Protected, High-Speed USB 2.0, 480Mbit/s, 1:2 Multiplexer/Demultiplexer switch with single enable", Manufacturer="TEXAS INSTRUMENTS", Manufacturer_Part_Number=TS3USB30EDGSR, Package=VSSOP-10
X1: library part MCD-01036, "Crystal, 24MHz, 6pF, +/-20ppm, 80R, 2x1.6mm", Manufacturer=NDK, Manufacturer_Part_Number=NX2016SA-24MHZ-EXS00A-CS10820, Package=2x1.6mm

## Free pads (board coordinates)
  round 0.508 on Mech16: 1(0.058,-75.847) 1(48.905,-75.847)

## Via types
v1: diameter 0.45, hole 0.2, Top Layer 1 Signal to Bottom Layer 4 Signal, tented both sides, 933 vias
v2: diameter 0.45, hole 0.2, Top Layer 1 Signal to Bottom Layer 4 Signal, tented bottom, 24 vias
v3: diameter 0.45/0/0/0.45 (per signal layer), hole 0.2, Top Layer 1 Signal to Bottom Layer 4 Signal, tented both sides, 12 vias

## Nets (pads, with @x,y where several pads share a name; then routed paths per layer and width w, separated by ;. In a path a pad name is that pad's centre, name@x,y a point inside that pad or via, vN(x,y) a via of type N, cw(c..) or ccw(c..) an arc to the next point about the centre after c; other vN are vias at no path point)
1V8_ST60_3: C15.2 C16.1 R24.2 U4.C3 U4.L3 | length 13.1
  Top Layer 1 Signal w0.19: v1(24.2,1.425) 24.468,1.693 24.468,1.914 24.713,2.158 24.803,2.158 U4.L3@24.815,2.17
  Top Layer 1 Signal w0.2: v1(24.2,5.575) 24.2,5.558 24.425,5.333 24.425,5.122 24.708,4.84 24.805,4.84 U4.C3@24.815,4.83
  Top Layer 1 Signal w0.4: R24.2@23.45,11.5 C15.2@23.45,9.375 v1(24.15,9.375)
  Bottom Layer 4 Signal w0.4: v1(24.15,9.375) 24.16,9.365 24.16,9.33 24.175,9.315 24.175,5.614 24.19,5.598 24.19,5.585 v1(24.2,5.575) v1@24.2,5.558 ; v1@24.175,5.366 23.675,4.866 23.675,2.058 24.19,1.543 24.19,1.435 v1(24.2,1.425)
